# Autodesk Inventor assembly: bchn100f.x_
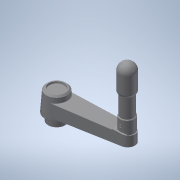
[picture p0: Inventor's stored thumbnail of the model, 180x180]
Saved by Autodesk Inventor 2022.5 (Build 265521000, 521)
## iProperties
Part Number: bchn100f.x_
Material: 一般
Document SubType Name: Assembly
Designer: ImaoCorp
Sending System: SOLIDWORKS 2017-2017317
MC: AMD64
MC_MODEL: Intel64 Family 6 Model 60 Stepping 3, GenuineIntel
OS: Windows_NT
FRU: Parasolid Version 29.0, build 201,  4-17-2017
FORMAT: text
GUISE: transmit
KEY: bchn100f
FILE: bchn100f.x_t
DATE: Fri Mar 15 10:33:49 2019
Author: ImaoCorp
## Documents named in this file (3)
- X:\14_SW2022-Inv2022\00_全2023-1023新製品(TCC)まで\b\bchn100f\BCHN100F.iam
- X:\14_SW2022-Inv2022\00_全2023-1023新製品(TCC)まで\b\bchn100f\bchn100f_01.ipt
- X:\14_SW2022-Inv2022\00_全2023-1023新製品(TCC)まで\b\bchn100f\bchn100f_02.ipt
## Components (2 placed, 2 different names)
1. bchn100f_01
2. bchn100f_02
